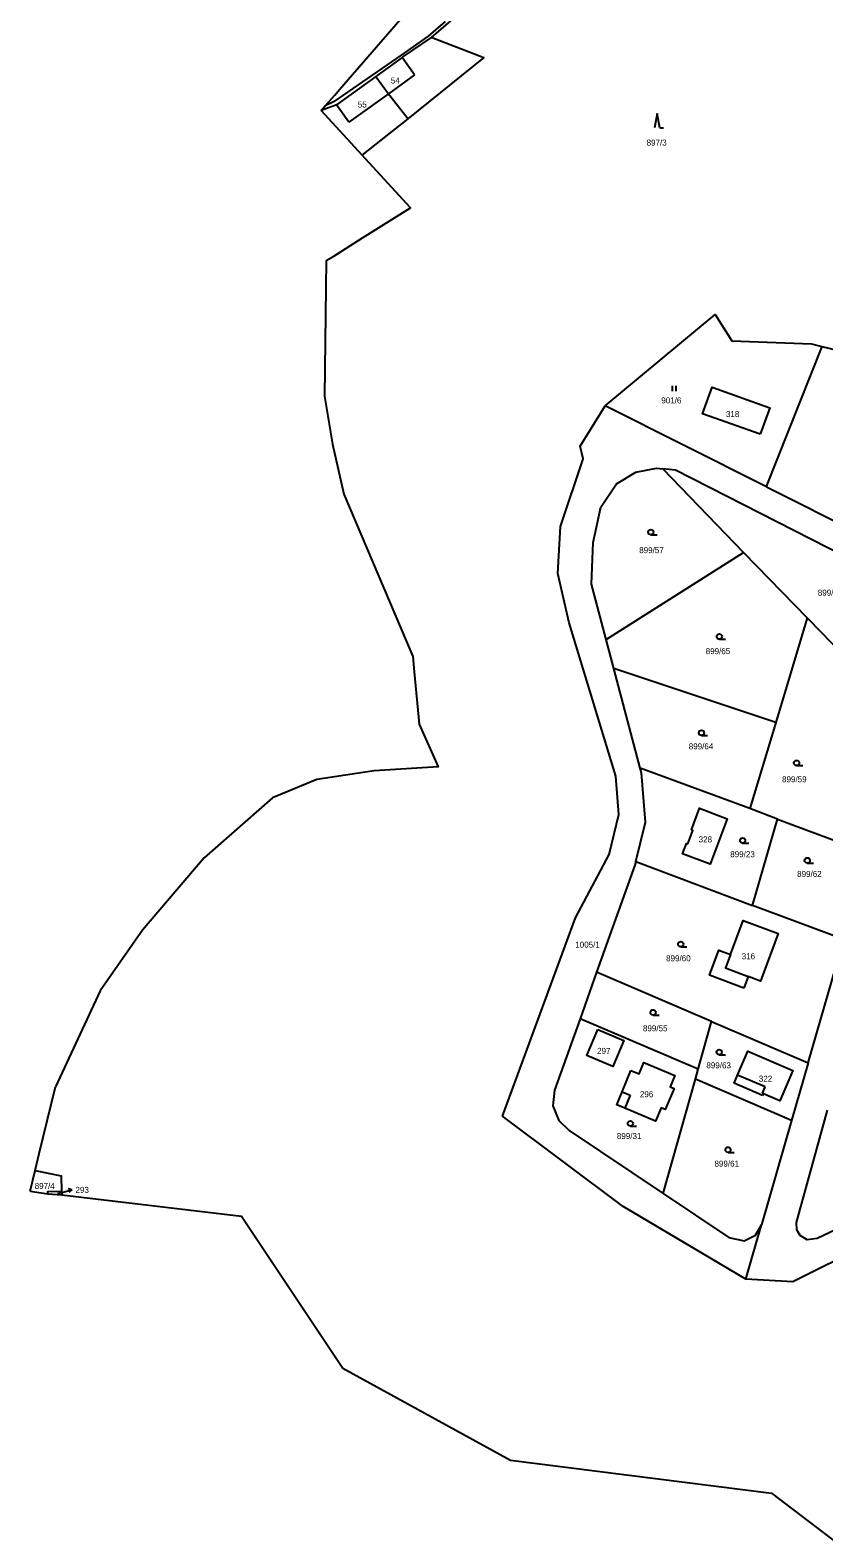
# Model space of a CAD drawing. Extents: x -7476540 to -746055, y -11317203 to -1129777.
# Drawn here: x -751332.8 to -751107.9, y -1131658.7 to -1131231.7 of the extents above; entities that cross this region are included whole.
import ezdxf

# ---------------------------------------------------------------- set-up
doc = ezdxf.new("R2010")
doc.units = 0
for name, color, linetype in [('Hranice parcel', 7, 'Continuous'), ('Parcelní čísla', 7, 'Continuous'), ('Pop  PČ popisy', 7, 'Continuous'), ('Vnitřní kresba', 7, 'Continuous'), ('Značky kultur', 7, 'Continuous')]:
    doc.layers.add(name, color=color, linetype=linetype)

msp = doc.modelspace()

# ---------------------------------------------------------------- linework, layer by layer
at = {"layer": 'Hranice parcel'}
for p, q in [((-751219.18, -1131233.85), (-751227.05, -1131239.2)), ((-751234.84, -1131244.82), (-751231.28, -1131249.74)), ((-751231.28, -1131249.74), (-751225.67, -1131256.87)), ((-751238.72, -1131267.16), (-751250.31, -1131254.5)), ((-751238.72, -1131267.16), (-751225.67, -1131256.87)), ((-751237.76, -1131268.21), (-751238.72, -1131267.16)), ((-751246.71, -1131295.77), (-751238.58, -1131290.51)), ((-751248.87, -1131296.96), (-751246.71, -1131295.77)), ((-751108.44, -1131321.29), (-751124.27, -1131360.98)), ((-751124.72, -1131360.76), (-751169.85, -1131338.1)), ((-751153.5, -1131356.01), (-751130.61, -1131379.62)), ((-751124.27, -1131360.98), (-751124.72, -1131360.76)), ((-751124.27, -1131360.98), (-751123.52, -1131361.36)), ((-751123.52, -1131361.36), (-751093.27, -1131376.55)), ((-751169.56, -1131404.33), (-751130.61, -1131379.62)), ((-751130.61, -1131379.62), (-751112.58, -1131398.2)), ((-751112.58, -1131398.2), (-751121.53, -1131427.82)), ((-751167.39, -1131412.53), (-751169.56, -1131404.33)), ((-751121.53, -1131427.82), (-751167.39, -1131412.53)), ((-751159.94, -1131440.74), (-751167.39, -1131412.53)), ((-751121.53, -1131427.82), (-751128.9, -1131452.2)), ((-751128.9, -1131452.2), (-751159.94, -1131440.74)), ((-751121.03, -1131455.15), (-751128.9, -1131452.2)), ((-751128.07, -1131479.61), (-751121.03, -1131455.15)), ((-751121.03, -1131455.15), (-751095.19, -1131464.83)), ((-751161.17, -1131467.21), (-751128.07, -1131479.61)), ((-751102.25, -1131489.28), (-751128.07, -1131479.61)), ((-751112.34, -1131524.21), (-751102.25, -1131489.28)), ((-751172.26, -1131498.57), (-751176.97, -1131511.75)), ((-751139.69, -1131512.5), (-751172.26, -1131498.57)), ((-751143.5, -1131526.03), (-751176.97, -1131511.75)), ((-751143.5, -1131526.03), (-751139.69, -1131512.5)), ((-751139.69, -1131512.5), (-751112.34, -1131524.21)), ((-751112.34, -1131524.21), (-751117.06, -1131540.57)), ((-751153.4, -1131561.23), (-751144.28, -1131528.8)), ((-751144.28, -1131528.8), (-751143.5, -1131526.03)), ((-751117.06, -1131540.57), (-751144.28, -1131528.8)), ((-751330.2, -1131549.91), (-751325.58, -1131531.02)), ((-751117.06, -1131540.57), (-751125.59, -1131570.11)), ((-751331.37, -1131554.68), (-751330.2, -1131549.91)), ((-751332.8, -1131560.55), (-751331.37, -1131554.68)), ((-751332.8, -1131560.55), (-751327.78, -1131561.29)), ((-751327.78, -1131561.29), (-751323.82, -1131561.58)), ((-751323.9, -1131560.54), (-751323.82, -1131561.58)), ((-751130.03, -1131585.48), (-751125.59, -1131570.11))]:
    msp.add_line(p, q, dxfattribs=at)
for points in [[(-751009.6, -1131338.57), (-751032.47, -1131291.34), (-751102.83, -1131142.08), (-751126.53, -1131105.01), (-751145.24, -1131089.25), (-751160.43, -1131079.74), (-751174.02, -1131076.23), (-751187.89, -1131082.29), (-751198.63, -1131092.32), (-751209.5, -1131105.94), (-751213.75, -1131135.97), (-751210.53, -1131194.07), (-751209.5, -1131224.85), (-751213.71, -1131229.1), (-751219.18, -1131233.85)], [(-751250.31, -1131254.5), (-751249.17, -1131253.18), (-751246.5, -1131250.1), (-751245.18, -1131248.58), (-751227.89, -1131228.61), (-751221.99, -1131221.8)], [(-751225.67, -1131256.87), (-751204.26, -1131239.61), (-751219.18, -1131233.85)], [(-751227.05, -1131239.2), (-751227.42, -1131239.46), (-751234.84, -1131244.82)], [(-751234.84, -1131244.82), (-751246, -1131252.89), (-751246.21, -1131252.97), (-751250.31, -1131254.5)], [(-751238.58, -1131290.51), (-751225.06, -1131282.09), (-751237.76, -1131268.21)], [(-751248.87, -1131296.96), (-751249.36, -1131335.38), (-751247.16, -1131348.97), (-751243.91, -1131363.12), (-751224.35, -1131409.09), (-751223.94, -1131413.42)], [(-751108.44, -1131321.29), (-751099.78, -1131323.39), (-751093.45, -1131310.33), (-751067.31, -1131327.1), (-751057.68, -1131328.84)], [(-751169.85, -1131338.1), (-751138.68, -1131312.27), (-751133.97, -1131319.71), (-751111.35, -1131320.58), (-751108.44, -1131321.29)], [(-751125.9, -1131346.18), (-751142.24, -1131340.37), (-751139.57, -1131332.85), (-751123.22, -1131338.65), (-751125.9, -1131346.18)], [(-751130.03, -1131585.48), (-751164.72, -1131564.87), (-751198.92, -1131539.35), (-751178.29, -1131483.11), (-751168.76, -1131465.17), (-751165.96, -1131453.86), (-751166.8, -1131443.05), (-751180.01, -1131399.61), (-751183.24, -1131385.66), (-751182.54, -1131372.3), (-751176.08, -1131353.12), (-751176.94, -1131349.57), (-751169.85, -1131338.1)], [(-751169.56, -1131404.33), (-751173.69, -1131388.67), (-751173.27, -1131376.88), (-751171.07, -1131366.83), (-751166.63, -1131360.22), (-751161.18, -1131356.88), (-751155.32, -1131355.82), (-751153.5, -1131356.01)], [(-751079.34, -1131409.92), (-751078.57, -1131404.84), (-751079.31, -1131398.59), (-751082.21, -1131392.91), (-751087.5, -1131388.18), (-751149.92, -1131356.39), (-751153.5, -1131356.01)], [(-751112.58, -1131398.2), (-751108.68, -1131402.23), (-751084.36, -1131427.31)], [(-751223.94, -1131413.42), (-751222.54, -1131428.3), (-751217.19, -1131440.38), (-751235.3, -1131441.48), (-751251.55, -1131444), (-751264.12, -1131449.18), (-751283.5, -1131466.12), (-751300.97, -1131486.67), (-751312.94, -1131503.8), (-751325.58, -1131531.02)], [(-751161.17, -1131467.21), (-751158.38, -1131456.03), (-751159.6, -1131442.04), (-751159.94, -1131440.74)], [(-751146.44, -1131462.22), (-751145.01, -1131458.39), (-751145.38, -1131458.25), (-751143.08, -1131452.09), (-751135.24, -1131455.05), (-751140.08, -1131467.97), (-751147.91, -1131465.01), (-751146.81, -1131462.08), (-751146.44, -1131462.22)], [(-751161.17, -1131467.21), (-751161.42, -1131468.2), (-751172.26, -1131498.57)], [(-751130.56, -1131503.05), (-751140.26, -1131499.4), (-751137.61, -1131492.3), (-751134.32, -1131493.51), (-751130.72, -1131483.89), (-751120.79, -1131487.6), (-751125.84, -1131501.04), (-751129.33, -1131499.74), (-751130.56, -1131503.05)], [(-751176.97, -1131511.75), (-751184.17, -1131531.9), (-751184.65, -1131536.34), (-751183, -1131540.5), (-751180.05, -1131543.39), (-751153.4, -1131561.23)], [(-751171.91, -1131514.73), (-751164.56, -1131517.86), (-751167.67, -1131525.21), (-751175.01, -1131522.08), (-751171.91, -1131514.73)], [(-751125.22, -1131533.44), (-751133.31, -1131529.96), (-751132.31, -1131527.65), (-751129.4, -1131520.89), (-751116.66, -1131526.35), (-751120.38, -1131534.94), (-751125, -1131532.94), (-751125.22, -1131533.44)], [(-751162.57, -1131526.37), (-751160.24, -1131527.34), (-751158.89, -1131524.12), (-751150.13, -1131527.82), (-751151.46, -1131530.97), (-751150.32, -1131531.44), (-751152.84, -1131537.43), (-751153.98, -1131536.98), (-751155.55, -1131540.73), (-751164.31, -1131537.02), (-751166.59, -1131536.05), (-751165.07, -1131532.39), (-751162.57, -1131526.37)], [(-751077.85, -1131574.67), (-751081.07, -1131571.51), (-751086.27, -1131568.56), (-751091.47, -1131567.23), (-751096.15, -1131567.52), (-751109.8, -1131573.95), (-751112.57, -1131574.29), (-751114.59, -1131573.08), (-751115.53, -1131571.46), (-751115.66, -1131569.38), (-751106.84, -1131537.6)], [(-751331.37, -1131554.68), (-751324.05, -1131556.19), (-751323.9, -1131560.54)], [(-751327.78, -1131561.29), (-751327.83, -1131560.65), (-751323.9, -1131560.54)], [(-751323.82, -1131561.58), (-751272.93, -1131567.59), (-751244.2, -1131610.68), (-751196.7, -1131636.78), (-751122.71, -1131646.1), (-751053.46, -1131698.72), (-751030.73, -1131701.58), (-751004.59, -1131712.2), (-750945.06, -1131720.15), (-750880.97, -1131755.87), (-750806.03, -1131757.06), (-750782.41, -1131781.2), (-750766.57, -1131788.17), (-750742.06, -1131786.93), (-750740.2, -1131775.46), (-750718.74, -1131766.85), (-750667.05, -1131813.02), (-750592.71, -1131860.77), (-750588.08, -1131875.75)], [(-751153.4, -1131561.23), (-751134.8, -1131573.69), (-751130.5, -1131574.62), (-751127.24, -1131573), (-751125.59, -1131570.11)], [(-751080.96, -1131586.15), (-751087.91, -1131576.56), (-751095.84, -1131575.81), (-751116.68, -1131586.24), (-751130.03, -1131585.48)]]:
    msp.add_lwpolyline(points, dxfattribs=at)
at = {"layer": 'Pop  PČ popisy'}
for p, q in [((-751324.99, -1131561.17), (-751323.85, -1131560.89)), ((-751323.85, -1131560.89), (-751320.94, -1131560.16)), ((-751320.94, -1131560.16), (-751322.03, -1131559.92)), ((-751320.94, -1131560.16), (-751321.79, -1131560.89))]:
    msp.add_line(p, q, dxfattribs=at)
at = {"layer": 'Vnitřní kresba'}
for p, q in [((-751215.17, -1131229.27), (-751220, -1131233.42)), ((-751220, -1131233.42), (-751227.7, -1131238.85)), ((-751227.7, -1131238.85), (-751246.85, -1131252.03)), ((-751223.87, -1131244.38), (-751227.42, -1131239.46)), ((-751223.87, -1131244.38), (-751231.28, -1131249.74)), ((-751231.28, -1131249.74), (-751242.45, -1131257.81)), ((-751246.85, -1131252.03), (-751249.17, -1131253.18)), ((-751242.45, -1131257.81), (-751246, -1131252.89)), ((-751124.52, -1131531), (-751132.31, -1131527.65)), ((-751165.07, -1131532.39), (-751162.77, -1131533.35)), ((-751162.77, -1131533.35), (-751164.31, -1131537.02)), ((-751125.3, -1131532.82), (-751124.52, -1131531)), ((-751125, -1131532.94), (-751125.3, -1131532.82))]:
    msp.add_line(p, q, dxfattribs=at)
msp.add_lwpolyline([(-751134.32, -1131493.51), (-751135.76, -1131497.34), (-751129.33, -1131499.74)], dxfattribs=at)
at = {"layer": 'Značky kultur'}
for p, q in [((-751155.09, -1131255.35), (-751155.84, -1131259.35)), ((-751154.34, -1131259.35), (-751155.09, -1131255.35)), ((-751154.34, -1131259.35), (-751153.34, -1131259.35)), ((-751150.75, -1131334), (-751150.75, -1131332.5)), ((-751149.75, -1131334), (-751149.75, -1131332.5)), ((-751156.9, -1131374.67), (-751155.15, -1131374.67)), ((-751137.48, -1131404.24), (-751135.73, -1131404.24)), ((-751142.56, -1131431.5), (-751140.81, -1131431.5)), ((-751115.6, -1131440.03), (-751113.85, -1131440.03)), ((-751130.89, -1131461.99), (-751129.14, -1131461.99)), ((-751112.59, -1131467.62), (-751110.84, -1131467.62)), ((-751148.43, -1131491.33), (-751146.68, -1131491.33)), ((-751156.28, -1131510.66), (-751154.53, -1131510.66)), ((-751137.53, -1131521.92), (-751135.78, -1131521.92)), ((-751162.7, -1131542.15), (-751160.95, -1131542.15)), ((-751135.04, -1131549.56), (-751133.29, -1131549.56))]:
    msp.add_line(p, q, dxfattribs=at)
for centre in [(-751156.9, -1131373.92), (-751137.48, -1131403.49), (-751142.56, -1131430.75), (-751115.6, -1131439.28), (-751130.89, -1131461.24), (-751112.59, -1131466.87), (-751148.43, -1131490.58), (-751156.28, -1131509.91), (-751137.53, -1131521.17), (-751162.7, -1131541.4), (-751135.04, -1131548.81)]:
    msp.add_circle(centre, 0.75, dxfattribs=at)

# ---------------------------------------------------------------- texts
at = {"layer": 'Parcelní čísla'}
for s, p in [('54', (-751230.58, -1131246.84)), ('55', (-751239.95, -1131253.64)), ('897/3', (-751158.1, -1131264.43)), ('901/6', (-751153.94, -1131337.45)), ('318', (-751135.62, -1131341.31)), ('899/57', (-751160.2, -1131379.85)), ('899/37', (-751109.59, -1131391.89)), ('899/65', (-751141.36, -1131408.45)), ('899/64', (-751146.16, -1131435.43)), ('899/59', (-751119.72, -1131444.75)), ('328', (-751143.36, -1131461.76)), ('899/23', (-751134.4, -1131465.96)), ('899/62', (-751115.45, -1131471.55)), ('1005/1', (-751178.32, -1131491.57)), ('899/60', (-751152.58, -1131495.45)), ('316', (-751131.16, -1131494.86)), ('899/55', (-751159.14, -1131515.26)), ('297', (-751172.14, -1131521.67)), ('899/63', (-751141.16, -1131525.76)), ('322', (-751126.3, -1131529.54)), ('296', (-751160.01, -1131533.95)), ('899/31', (-751166.53, -1131545.78)), ('899/61', (-751138.87, -1131553.6)), ('897/4', (-751331.51, -1131559.92)), ('293', (-751319.94, -1131561.03))]:
    msp.add_text(s, height=1.7, dxfattribs=at).set_placement(p)

doc.saveas('drawing.dxf')
